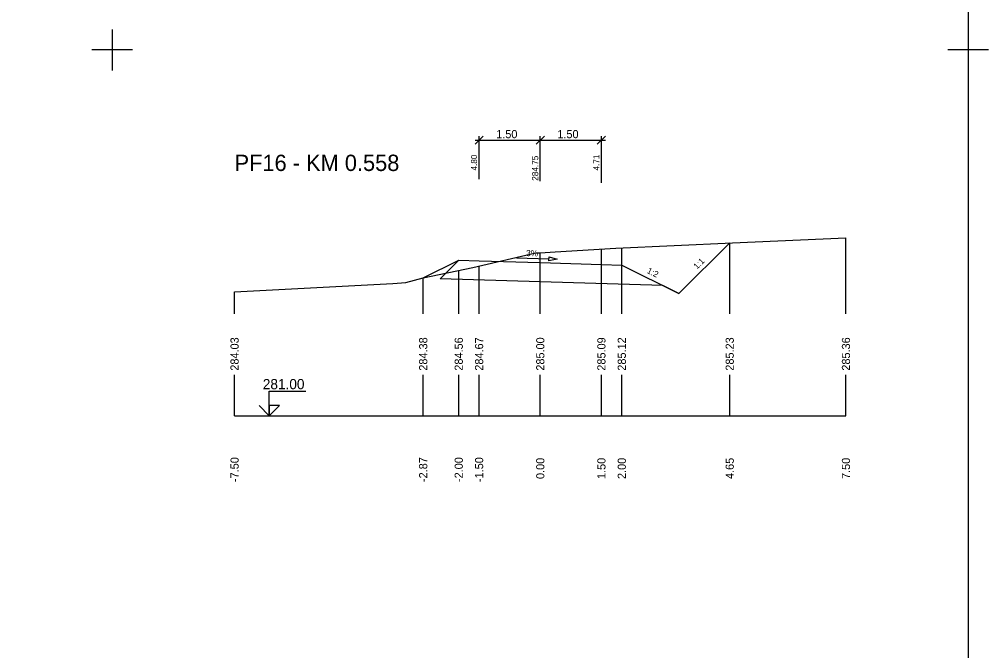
# Model space of a CAD drawing. Extents: x -5 to 1265, y -2 to 602.
# Drawn here: x 1027.2 to 1265, y 152.4 to 307.2 of the extents above; entities that cross this region are included whole.
import ezdxf

# ---------------------------------------------------------------- set-up
doc = ezdxf.new("R2010")
doc.units = 0
for name, color, linetype in [('KOTA', 7, 'Continuous'), ('KOTA_DELKY', 7, 'Continuous'), ('KOTA_DELKY_CONT', 7, 'Continuous'), ('NS_TELESO_VOZOVKY', 7, 'Continuous'), ('NS_V_PF', 7, 'Continuous'), ('REZY_PF_PUVODNI', 7, 'Continuous'), ('SESTAVY_REZU_PF', 7, 'Continuous'), ('SKLON', 7, 'Continuous'), ('SVK', 7, 'Continuous')]:
    doc.layers.add(name, color=color, linetype=linetype)

msp = doc.modelspace()

# ---------------------------------------------------------------- linework, layer by layer
for p, q in [((1050, 304.67), (1050, 294.67)), ((1050, 304.67), (1050, 294.67)), ((1050, 304.67), (1050, 294.67)), ((1050, 304.67), (1050, 294.67)), ((1050, 304.67), (1050, 294.67)), ((1050, 304.67), (1050, 294.67)), ((1050, 304.67), (1050, 294.67)), ((1050, 304.67), (1050, 294.67)), ((1050, 304.67), (1050, 294.67)), ((1050, 304.67), (1050, 294.67)), ((1050, 304.67), (1050, 294.67)), ((1050, 304.67), (1050, 294.67)), ((1050, 304.67), (1050, 294.67)), ((1050, 304.67), (1050, 294.67)), ((1050, 304.67), (1050, 294.67)), ((1050, 304.67), (1050, 294.67)), ((1050, 304.67), (1050, 294.67)), ((1050, 304.67), (1050, 294.67)), ((1050, 304.67), (1050, 294.67)), ((1050, 304.67), (1050, 294.67)), ((1050, 304.67), (1050, 294.67)), ((1050, 304.67), (1050, 294.67)), ((1050, 304.67), (1050, 294.67)), ((1050, 304.67), (1050, 294.67)), ((1050, 304.67), (1050, 294.67)), ((1050, 304.67), (1050, 294.67)), ((1050, 304.67), (1050, 294.67)), ((1050, 304.67), (1050, 294.67)), ((1050, 304.67), (1050, 294.67)), ((1050, 304.67), (1050, 294.67)), ((1050, 304.67), (1050, 294.67)), ((1050, 304.67), (1050, 294.67)), ((1050, 304.67), (1050, 294.67)), ((1050, 304.67), (1050, 294.67)), ((1050, 304.67), (1050, 294.67)), ((1050, 304.67), (1050, 294.67)), ((1050, 304.67), (1050, 294.67)), ((1050, 304.67), (1050, 294.67)), ((1050, 304.67), (1050, 294.67)), ((1050, 304.67), (1050, 294.67)), ((1050, 304.67), (1050, 294.67)), ((1050, 304.67), (1050, 294.67)), ((1050, 304.67), (1050, 294.67)), ((1050, 304.67), (1050, 294.67)), ((1050, 304.67), (1050, 294.67)), ((1050, 304.67), (1050, 294.67)), ((1050, 304.67), (1050, 294.67)), ((1050, 304.67), (1050, 294.67)), ((1050, 304.67), (1050, 294.67)), ((1050, 304.67), (1050, 294.67)), ((1050, 304.67), (1050, 294.67)), ((1050, 304.67), (1050, 294.67)), ((1050, 304.67), (1050, 294.67)), ((1050, 304.67), (1050, 294.67)), ((1050, 304.67), (1050, 294.67)), ((1050, 304.67), (1050, 294.67)), ((1050, 304.67), (1050, 294.67)), ((1050, 304.67), (1050, 294.67)), ((1050, 304.67), (1050, 294.67)), ((1050, 304.67), (1050, 294.67)), ((1050, 304.67), (1050, 294.67)), ((1050, 304.67), (1050, 294.67)), ((1050, 304.67), (1050, 294.67)), ((1050, 304.67), (1050, 294.67)), ((1050, 304.67), (1050, 294.67)), ((1050, 304.67), (1050, 294.67)), ((1260, 304.67), (1260, 294.67)), ((1260, 304.67), (1260, 294.67)), ((1260, 304.67), (1260, 294.67)), ((1260, 304.67), (1260, 294.67)), ((1260, 304.67), (1260, 294.67)), ((1260, 304.67), (1260, 294.67)), ((1260, 304.67), (1260, 294.67)), ((1260, 304.67), (1260, 294.67)), ((1260, 304.67), (1260, 294.67)), ((1260, 304.67), (1260, 294.67)), ((1260, 304.67), (1260, 294.67)), ((1260, 304.67), (1260, 294.67)), ((1260, 304.67), (1260, 294.67)), ((1260, 304.67), (1260, 294.67)), ((1260, 304.67), (1260, 294.67)), ((1260, 304.67), (1260, 294.67)), ((1260, 304.67), (1260, 294.67)), ((1260, 304.67), (1260, 294.67)), ((1260, 304.67), (1260, 294.67)), ((1260, 304.67), (1260, 294.67)), ((1260, 304.67), (1260, 294.67)), ((1260, 304.67), (1260, 294.67)), ((1260, 304.67), (1260, 294.67)), ((1260, 304.67), (1260, 294.67)), ((1260, 304.67), (1260, 294.67)), ((1260, 304.67), (1260, 294.67)), ((1260, 304.67), (1260, 294.67)), ((1260, 304.67), (1260, 294.67)), ((1260, 304.67), (1260, 294.67)), ((1260, 304.67), (1260, 294.67)), ((1260, 304.67), (1260, 294.67)), ((1260, 304.67), (1260, 294.67)), ((1260, 304.67), (1260, 294.67)), ((1260, 304.67), (1260, 294.67)), ((1260, 304.67), (1260, 294.67)), ((1260, 304.67), (1260, 294.67)), ((1260, 304.67), (1260, 294.67)), ((1260, 304.67), (1260, 294.67)), ((1260, 304.67), (1260, 294.67)), ((1260, 304.67), (1260, 294.67)), ((1260, 304.67), (1260, 294.67)), ((1260, 304.67), (1260, 294.67)), ((1260, 304.67), (1260, 294.67)), ((1260, 304.67), (1260, 294.67)), ((1260, 304.67), (1260, 294.67)), ((1260, 304.67), (1260, 294.67)), ((1260, 304.67), (1260, 294.67)), ((1260, 304.67), (1260, 294.67)), ((1260, 304.67), (1260, 294.67)), ((1260, 304.67), (1260, 294.67)), ((1260, 304.67), (1260, 294.67)), ((1260, 304.67), (1260, 294.67)), ((1260, 304.67), (1260, 294.67)), ((1260, 304.67), (1260, 294.67)), ((1260, 304.67), (1260, 294.67)), ((1260, 304.67), (1260, 294.67)), ((1260, 304.67), (1260, 294.67)), ((1260, 304.67), (1260, 294.67)), ((1260, 304.67), (1260, 294.67)), ((1260, 304.67), (1260, 294.67)), ((1260, 304.67), (1260, 294.67)), ((1260, 304.67), (1260, 294.67)), ((1260, 304.67), (1260, 294.67)), ((1260, 304.67), (1260, 294.67)), ((1260, 304.67), (1260, 294.67)), ((1260, 304.67), (1260, 294.67)), ((1260, 304.67), (1260, 294.67)), ((1260, 304.67), (1260, 294.67)), ((1260, 304.67), (1260, 294.67)), ((1260, 304.67), (1260, 294.67)), ((1055, 299.67), (1045, 299.67)), ((1055, 299.67), (1045, 299.67)), ((1055, 299.67), (1045, 299.67)), ((1055, 299.67), (1045, 299.67)), ((1055, 299.67), (1045, 299.67)), ((1055, 299.67), (1045, 299.67)), ((1055, 299.67), (1045, 299.67)), ((1055, 299.67), (1045, 299.67)), ((1055, 299.67), (1045, 299.67)), ((1055, 299.67), (1045, 299.67)), ((1055, 299.67), (1045, 299.67)), ((1055, 299.67), (1045, 299.67)), ((1055, 299.67), (1045, 299.67)), ((1055, 299.67), (1045, 299.67)), ((1055, 299.67), (1045, 299.67)), ((1055, 299.67), (1045, 299.67)), ((1055, 299.67), (1045, 299.67)), ((1055, 299.67), (1045, 299.67)), ((1055, 299.67), (1045, 299.67)), ((1055, 299.67), (1045, 299.67)), ((1055, 299.67), (1045, 299.67)), ((1055, 299.67), (1045, 299.67)), ((1055, 299.67), (1045, 299.67)), ((1055, 299.67), (1045, 299.67)), ((1055, 299.67), (1045, 299.67)), ((1055, 299.67), (1045, 299.67)), ((1055, 299.67), (1045, 299.67)), ((1055, 299.67), (1045, 299.67)), ((1055, 299.67), (1045, 299.67)), ((1055, 299.67), (1045, 299.67)), ((1055, 299.67), (1045, 299.67)), ((1055, 299.67), (1045, 299.67)), ((1055, 299.67), (1045, 299.67)), ((1055, 299.67), (1045, 299.67)), ((1055, 299.67), (1045, 299.67)), ((1055, 299.67), (1045, 299.67)), ((1055, 299.67), (1045, 299.67)), ((1055, 299.67), (1045, 299.67)), ((1055, 299.67), (1045, 299.67)), ((1055, 299.67), (1045, 299.67)), ((1055, 299.67), (1045, 299.67)), ((1055, 299.67), (1045, 299.67)), ((1055, 299.67), (1045, 299.67)), ((1055, 299.67), (1045, 299.67)), ((1055, 299.67), (1045, 299.67)), ((1055, 299.67), (1045, 299.67)), ((1055, 299.67), (1045, 299.67)), ((1055, 299.67), (1045, 299.67)), ((1055, 299.67), (1045, 299.67)), ((1055, 299.67), (1045, 299.67)), ((1055, 299.67), (1045, 299.67)), ((1055, 299.67), (1045, 299.67)), ((1055, 299.67), (1045, 299.67)), ((1055, 299.67), (1045, 299.67)), ((1055, 299.67), (1045, 299.67)), ((1055, 299.67), (1045, 299.67)), ((1055, 299.67), (1045, 299.67)), ((1055, 299.67), (1045, 299.67)), ((1055, 299.67), (1045, 299.67)), ((1055, 299.67), (1045, 299.67)), ((1055, 299.67), (1045, 299.67)), ((1055, 299.67), (1045, 299.67)), ((1055, 299.67), (1045, 299.67)), ((1055, 299.67), (1045, 299.67)), ((1055, 299.67), (1045, 299.67)), ((1055, 299.67), (1045, 299.67)), ((1265, 299.67), (1255, 299.67)), ((1265, 299.67), (1255, 299.67)), ((1265, 299.67), (1255, 299.67)), ((1265, 299.67), (1255, 299.67)), ((1265, 299.67), (1255, 299.67)), ((1265, 299.67), (1255, 299.67)), ((1265, 299.67), (1255, 299.67)), ((1265, 299.67), (1255, 299.67)), ((1265, 299.67), (1255, 299.67)), ((1265, 299.67), (1255, 299.67)), ((1265, 299.67), (1255, 299.67)), ((1265, 299.67), (1255, 299.67)), ((1265, 299.67), (1255, 299.67)), ((1265, 299.67), (1255, 299.67)), ((1265, 299.67), (1255, 299.67)), ((1265, 299.67), (1255, 299.67)), ((1265, 299.67), (1255, 299.67)), ((1265, 299.67), (1255, 299.67)), ((1265, 299.67), (1255, 299.67)), ((1265, 299.67), (1255, 299.67)), ((1265, 299.67), (1255, 299.67)), ((1265, 299.67), (1255, 299.67)), ((1265, 299.67), (1255, 299.67)), ((1265, 299.67), (1255, 299.67)), ((1265, 299.67), (1255, 299.67)), ((1265, 299.67), (1255, 299.67)), ((1265, 299.67), (1255, 299.67)), ((1265, 299.67), (1255, 299.67)), ((1265, 299.67), (1255, 299.67)), ((1265, 299.67), (1255, 299.67)), ((1265, 299.67), (1255, 299.67)), ((1265, 299.67), (1255, 299.67)), ((1265, 299.67), (1255, 299.67)), ((1265, 299.67), (1255, 299.67)), ((1265, 299.67), (1255, 299.67)), ((1265, 299.67), (1255, 299.67)), ((1265, 299.67), (1255, 299.67)), ((1265, 299.67), (1255, 299.67)), ((1265, 299.67), (1255, 299.67)), ((1265, 299.67), (1255, 299.67)), ((1265, 299.67), (1255, 299.67)), ((1265, 299.67), (1255, 299.67)), ((1265, 299.67), (1255, 299.67)), ((1265, 299.67), (1255, 299.67)), ((1265, 299.67), (1255, 299.67)), ((1265, 299.67), (1255, 299.67)), ((1265, 299.67), (1255, 299.67)), ((1265, 299.67), (1255, 299.67)), ((1265, 299.67), (1255, 299.67)), ((1265, 299.67), (1255, 299.67)), ((1265, 299.67), (1255, 299.67)), ((1265, 299.67), (1255, 299.67)), ((1265, 299.67), (1255, 299.67)), ((1265, 299.67), (1255, 299.67)), ((1265, 299.67), (1255, 299.67)), ((1265, 299.67), (1255, 299.67)), ((1265, 299.67), (1255, 299.67)), ((1265, 299.67), (1255, 299.67)), ((1265, 299.67), (1255, 299.67)), ((1265, 299.67), (1255, 299.67)), ((1265, 299.67), (1255, 299.67)), ((1265, 299.67), (1255, 299.67)), ((1265, 299.67), (1255, 299.67)), ((1265, 299.67), (1255, 299.67)), ((1265, 299.67), (1255, 299.67)), ((1265, 299.67), (1255, 299.67)), ((1265, 299.67), (1255, 299.67)), ((1265, 299.67), (1255, 299.67)), ((1265, 299.67), (1255, 299.67)), ((1265, 299.67), (1255, 299.67))]:
    msp.add_line(p, q)
msp.add_lwpolyline([(0, 596.67), (1260, 596.67), (1260, 2.67), (0, 2.67)], close=True)
at = {"layer": 'KOTA'}
for points in [[(1088.51, 210), (1086.01, 212.5), (1088.51, 210), (1088.51, 216), (1097.51, 216)], [(1088.51, 210), (1091.01, 212.5), (1088.51, 212.5), (1088.51, 210)], [(1088.51, 210), (1091.01, 212.5), (1088.51, 212.5)]]:
    msp.add_lwpolyline(points, dxfattribs=at)
at = {"layer": 'KOTA_DELKY'}
for points in [[(1139, 276.54), (1141, 278.54)], [(1140, 267.99), (1140, 278.54)], [(1154, 276.54), (1156, 278.54)], [(1154, 276.54), (1156, 278.54)], [(1155, 267.54), (1155, 278.54)], [(1155, 267.54), (1155, 278.54)], [(1169, 276.54), (1171, 278.54)], [(1170, 267.09), (1170, 278.54)], [(1139, 277.54), (1156, 277.54)], [(1154, 277.54), (1171, 277.54)]]:
    msp.add_lwpolyline(points, dxfattribs=at)
at = {"layer": 'NS_TELESO_VOZOVKY'}
msp.add_lwpolyline([(1155, 247.54), (1170, 247.09), (1175, 246.94), (1189.01, 240), (1185.11, 241.93), (1155, 242.84), (1130.44, 243.57), (1135, 248.14), (1140, 247.99), (1155, 247.54)], dxfattribs=at)
at = {"layer": 'NS_V_PF'}
msp.add_lwpolyline([(1126.28, 243.78), (1135, 248.14), (1140, 247.99), (1155, 247.54), (1170, 247.09), (1175, 246.94), (1189.01, 240), (1201.48, 252.35)], dxfattribs=at)
at = {"layer": 'REZY_PF_PUVODNI'}
msp.add_lwpolyline([(1080, 240.35), (1118.82, 242.46), (1122.02, 242.63), (1126.24, 243.77), (1138.47, 246.33), (1153.9, 249.91), (1155, 249.97), (1155, 249.97), (1158.65, 250.17), (1173.52, 251.12), (1202.16, 252.38), (1230, 253.6)], dxfattribs=at)
at = {"layer": 'SESTAVY_REZU_PF'}
msp.add_lwpolyline([(1080, 210), (1230, 210)], dxfattribs=at)
at = {"layer": 'SKLON'}
for points in [[(1149.15, 248.71), (1157.14, 248.47)], [(1157.16, 248.97), (1159.14, 248.41), (1157.13, 247.97), (1157.16, 248.97)]]:
    msp.add_lwpolyline(points, dxfattribs=at)
msp.add_lwpolyline([(1157.16, 248.97), (1159.14, 248.41), (1157.13, 247.97)], close=True, dxfattribs=at)
at = {"layer": 'SVK'}
for points in [[(1201.48, 235), (1201.48, 252.35)], [(1230, 235), (1230, 253.6)], [(1155, 235), (1155, 249.97)], [(1170, 235), (1170, 250.9)], [(1175, 235), (1175, 251.19)], [(1135, 235), (1135, 245.6)], [(1140, 235), (1140, 246.69)], [(1126.28, 235), (1126.28, 243.78)], [(1080, 235), (1080, 240.35)], [(1080, 210), (1080, 220)], [(1126.28, 210), (1126.28, 220)], [(1135, 210), (1135, 220)], [(1140, 210), (1140, 220)], [(1155, 210), (1155, 220)], [(1170, 210), (1170, 220)], [(1175, 210), (1175, 220)], [(1201.48, 210), (1201.48, 220)], [(1230, 210), (1230, 220)]]:
    msp.add_lwpolyline(points, dxfattribs=at)

# ---------------------------------------------------------------- texts
at = {"layer": 'KOTA'}
msp.add_text('281.00', height=2.5, dxfattribs=at).set_placement((1086.93, 216.5))
at = {"layer": 'KOTA_DELKY'}
for p in [(1144.19, 278.04), (1159.19, 278.04)]:
    msp.add_text('1.50', height=2, dxfattribs=at).set_placement(p)
at = {"layer": 'KOTA_DELKY_CONT'}
for s, p in [('4.80', (1139.5, 270.12)), ('284.75', (1154.5, 267.61)), ('4.71', (1169.5, 270.12))]:
    msp.add_text(s, height=1.5, rotation=90, dxfattribs=at).set_placement(p)
at = {"layer": 'SESTAVY_REZU_PF'}
msp.add_text('PF16 - KM 0.558', height=4, dxfattribs=at).set_placement((1080, 270))
at = {"layer": 'SKLON'}
for s, rotation, p in [('3%', 358.2816, (1151.52, 249.14)), ('1:1', 44.7149, (1193.45, 245.81)), ('1:2', 333.679, (1181.04, 245.06))]:
    msp.add_text(s, height=1.5, rotation=rotation, dxfattribs=at).set_placement(p)
at = {"layer": 'SVK'}
for s, p in [(' 284.03', (1081, 220.3)), (' 284.38', (1127.28, 220.3)), (' 284.56', (1136, 220.3)), (' 284.67', (1141, 220.3)), (' 285.00', (1156, 220.3)), (' 285.09', (1171, 220.3)), (' 285.12', (1176, 220.3)), (' 285.23', (1202.48, 220.3)), (' 285.36', (1231, 220.3)), (' -7.50', (1081, 193)), (' -2.87', (1127.28, 193)), (' -2.00', (1136, 193)), (' -1.50', (1141, 193)), ('  0.00', (1156, 193)), ('  1.50', (1171, 193)), ('  2.00', (1176, 193)), ('  4.65', (1202.48, 193)), ('  7.50', (1231, 193))]:
    msp.add_text(s, height=2, rotation=90, dxfattribs=at).set_placement(p)

doc.saveas('drawing.dxf')
